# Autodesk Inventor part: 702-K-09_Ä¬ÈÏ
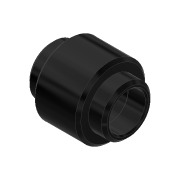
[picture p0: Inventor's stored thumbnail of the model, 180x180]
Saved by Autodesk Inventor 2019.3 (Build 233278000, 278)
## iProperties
Created: 2010-06
Part Number: 702-K-09_Ä¬ÈÏ
Material: Ogólny
Document SubType Name: Modeling
Designer: CADENGINEERING4
Density: 1 g/cm^3
Appearance: Gładki — czarny
Author: CADENGINEERING4
Revision Number: ÈÎºÎ
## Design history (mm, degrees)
feature "NONE"
node "Bryła1"
